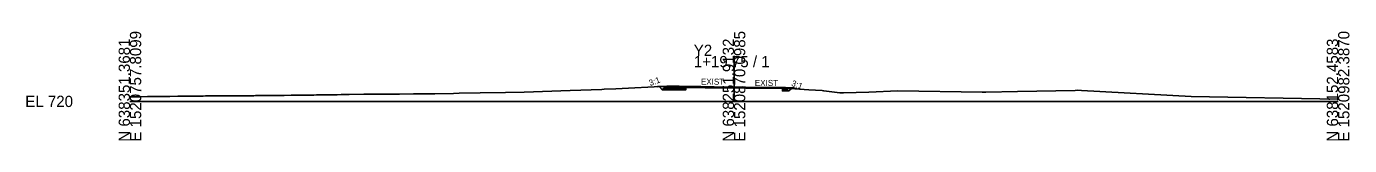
# Model space of a CAD drawing. Extents: x -26 to 1603, y -10 to 1019.
# Drawn here: x 1274.3 to 1602.8, y -9.7 to 17.3 of the extents above; entities that cross this region are included whole.
import ezdxf

# ---------------------------------------------------------------- set-up
doc = ezdxf.new("R2010")
doc.units = 0
for name, color, linetype in [('Exist Cross Section Cell', 7, 'Continuous'), ('Exist XS Center Line Elevation Label', 7, 'Continuous'), ('Exist XS Ground Line', 7, 'Continuous'), ('Prop CMT Pvmt Course 1', 7, 'Continuous'), ('Prop CMT Pvmt Course 2', 7, 'Continuous'), ('Prop CMT Pvmt Course 3', 7, 'Continuous'), ('Prop CMT Pvmt Surface', 7, 'Continuous'), ('Prop CMT Slope Grass', 7, 'Continuous'), ('Prop CMT Subgrade Earthwork', 7, 'Continuous'), ('Prop XS Earthwork Shape', 7, 'Continuous')]:
    doc.layers.add(name, color=color, linetype=linetype)

msp = doc.modelspace()

# ---------------------------------------------------------------- linework, layer by layer
at = {"layer": 'Exist Cross Section Cell'}
for p, q in [((1450, 0), (1450, 11.28)), ((1300, 0), (1450, 0)), ((1450, 0), (1600, 0))]:
    msp.add_line(p, q, dxfattribs=at)
at = {"layer": 'Exist XS Ground Line'}
msp.add_lwpolyline([(1300, 1.14), (1300.59, 1.15), (1301.05, 1.15), (1301.46, 1.15), (1302.83, 1.16), (1304.36, 1.18), (1304.8, 1.19), (1306.36, 1.19), (1308.15, 1.22), (1309.91, 1.23), (1311.92, 1.26), (1313.46, 1.29), (1314.83, 1.3), (1315.69, 1.31), (1318.16, 1.33), (1318.74, 1.34), (1319.4, 1.34), (1321.5, 1.36), (1322.29, 1.36), (1323.18, 1.37), (1324.08, 1.37), (1324.85, 1.38), (1325.87, 1.39), (1326.99, 1.4), (1328.18, 1.41), (1329.4, 1.41), (1330.79, 1.42), (1331.17, 1.43), (1331.51, 1.43), (1332.94, 1.44), (1334.86, 1.45), (1337.24, 1.48), (1338.31, 1.49), (1340.02, 1.51), (1341.67, 1.53), (1342.12, 1.53), (1343.59, 1.55), (1344.83, 1.56), (1345.64, 1.58), (1346.33, 1.59), (1347.52, 1.61), (1348.65, 1.62), (1349.62, 1.64), (1349.92, 1.65), (1351.46, 1.67), (1352.48, 1.68), (1353.48, 1.69), (1354.43, 1.71), (1358.12, 1.76), (1362.13, 1.8), (1366.93, 1.82), (1370.41, 1.84), (1372.15, 1.84), (1375.74, 1.89), (1380.34, 2), (1381.78, 2.03), (1386.93, 2.11), (1393.29, 2.21), (1397.9, 2.33), (1409.32, 2.67), (1417.18, 2.98), (1417.72, 3), (1420.67, 3.14), (1433.33, 3.75), (1434.78, 3.75), (1435.14, 3.76), (1436.37, 3.74), (1438.03, 3.73), (1438.83, 3.72), (1440.13, 3.7), (1441.75, 3.68), (1443.9, 3.63), (1445.08, 3.6), (1447.64, 3.57), (1448.52, 3.56), (1449.62, 3.57), (1450, 3.56), (1451.73, 3.53), (1453.35, 3.49), (1455.17, 3.44), (1456.89, 3.4), (1458.95, 3.36), (1461.58, 3.31), (1462.16, 3.3), (1462.81, 3.28), (1468.56, 2.9), (1471.85, 2.69), (1472.27, 2.61), (1476.28, 2.09), (1477.21, 2.12), (1483.47, 2.31), (1490.64, 2.61), (1511.63, 2.28), (1512.56, 2.28), (1520.41, 2.44), (1534.75, 2.74), (1535.31, 2.75), (1536.29, 2.71), (1563.48, 1.18), (1600, 0.59)], dxfattribs=at)
at = {"layer": 'Prop CMT Pvmt Course 1'}
msp.add_line((1433, 3.73), (1462.81, 3.43), dxfattribs=at)
at = {"layer": 'Prop CMT Pvmt Course 2'}
msp.add_line((1432.75, 3.48), (1463.06, 3.18), dxfattribs=at)
at = {"layer": 'Prop CMT Pvmt Course 3'}
for p, q in [((1438, 3.68), (1438, 2.85)), ((1462, 2.61), (1462, 3.44)), ((1432.43, 3.16), (1438, 3.1)), ((1462, 2.86), (1463.4, 2.85))]:
    msp.add_line(p, q, dxfattribs=at)
at = {"layer": 'Prop CMT Pvmt Surface'}
msp.add_line((1433, 3.73), (1462.81, 3.43), dxfattribs=at)
at = {"layer": 'Prop CMT Slope Grass'}
for p, q in [((1431, 3.66), (1430.91, 3.63)), ((1433, 3.73), (1431, 3.66)), ((1462.81, 3.43), (1464.81, 3.36)), ((1464.81, 3.36), (1465.61, 3.1))]:
    msp.add_line(p, q, dxfattribs=at)
at = {"layer": 'Prop CMT Subgrade Earthwork'}
for p, q in [((1432.18, 2.91), (1431.41, 3.68)), ((1433, 3.73), (1432.18, 2.92)), ((1462, 3.19), (1438, 3.43)), ((1438, 3.43), (1438, 2.85)), ((1462.81, 3.43), (1463.65, 2.59)), ((1463.65, 2.59), (1464.43, 3.38)), ((1432.18, 2.91), (1438, 2.85)), ((1462, 2.61), (1462, 3.19)), ((1462, 2.61), (1463.65, 2.59))]:
    msp.add_line(p, q, dxfattribs=at)
at = {"layer": 'Prop XS Earthwork Shape'}
for points in [[(1431, 3.66), (1430.91, 3.63), (1431.43, 3.66), (1431.41, 3.68)], [(1433, 3.73), (1432.18, 2.92), (1431.43, 3.66)], [(1433, 3.73), (1432.18, 2.92), (1438, 2.85), (1438, 3.43), (1462, 3.19), (1462, 2.61), (1463.65, 2.59), (1462.97, 3.27), (1462.81, 3.28), (1462.16, 3.3), (1461.58, 3.31), (1458.95, 3.36), (1456.89, 3.4), (1455.17, 3.44), (1453.35, 3.49), (1451.73, 3.53), (1450, 3.56), (1449.41, 3.57), (1448.52, 3.56), (1447.64, 3.57), (1445.08, 3.6), (1444.14, 3.62)], [(1435.14, 3.76), (1436.37, 3.74), (1438.03, 3.73), (1438.83, 3.72), (1440.13, 3.7), (1441.75, 3.68), (1443.9, 3.63), (1444.14, 3.62), (1433, 3.73), (1433.33, 3.75), (1434.78, 3.75)], [(1449.62, 3.57), (1450, 3.56), (1449.41, 3.57)], [(1464.81, 3.36), (1465.61, 3.1), (1464.25, 3.19), (1464.43, 3.38)], [(1463.65, 2.59), (1464.25, 3.19), (1462.97, 3.27)]]:
    msp.add_lwpolyline(points, close=True, dxfattribs=at)

# ---------------------------------------------------------------- texts
at = {"layer": 'Exist Cross Section Cell'}
for s, p in [('E 1520757.8099', (1302.8, -10)), ('E 1520870.0985', (1452.8, -10)), ('E 1520982.3870', (1602.8, -10)), ('N 638351.3681', (1300, -10)), ('N 638251.9132', (1450, -10)), ('N 638152.4583', (1600, -10))]:
    msp.add_text(s, height=2.8, rotation=90, dxfattribs=at).set_placement(p)
for s, p in [('Y2', (1440, 11.28)), ('1+19.75 / 1', (1440, 8.48)), ('EL 720', (1274, -1.4))]:
    msp.add_text(s, height=2.8, dxfattribs=at).set_placement(p)
at = {"layer": 'Exist XS Center Line Elevation Label'}
for s, rotation, p in [('3:1', 19.8357, (1429.19, 3.8)), ('EXIST', 359.8103, (1441.77, 4.15)), ('EXIST', 359.8103, (1455.16, 3.85)), ('3:1', 340.1643, (1464.11, 3.92))]:
    msp.add_text(s, height=1.5, rotation=rotation, dxfattribs=at).set_placement(p)

doc.saveas('drawing.dxf')
